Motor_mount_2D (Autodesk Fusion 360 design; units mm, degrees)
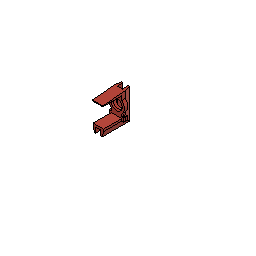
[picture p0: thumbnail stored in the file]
base_feature "Base Feature"
sketch "Sketch1" plane through (0, 0, 0) normal (1, 0, 0) x axis (0, 0, -1)
  dimension "d93" = 14
extrude "Extrude1" new body sketch "Sketch1" distance 8
sketch "Sketch5" plane through (0, 0, -47.8449) normal (0, 0, 1) x axis (1, 0, 0)
  dimension "d107" = 12
extrude "Extrude4" add sketch "Sketch5" to an object
sketch "Sketch2" plane through (2, 0, 0) normal (1, 0, 0) x axis (0, 0, -1)
  dimension "d96" = 4
extrude "Extrude2" add sketch "Sketch2" to an object
chamfer "Chamfer1" distance 1 distance 4
mirror "Mirror1"
sketch "Sketch3" plane through (0, 0, -47.8449) normal (0, 0, 1) x axis (1, 0, 0)
extrude "Extrude3" cut sketch "Sketch3" against normal blind 3
chamfer "Chamfer2" distance 0.9
sketch "Sketch7" plane through (4, 0, 0) normal (1, 0, 0) x axis (0, 0, -1)
  dimension "d113" = 0.6
extrude "Extrude5" cut sketch "Sketch7" no distance stored
sketch "Sketch8" plane through (4, 0, 0) normal (1, 0, 0) x axis (0, 0, -1)
  dimension "d115" = 3
extrude "Extrude6" add sketch "Sketch8" along normal blind 1.5
mirror "Mirror2"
